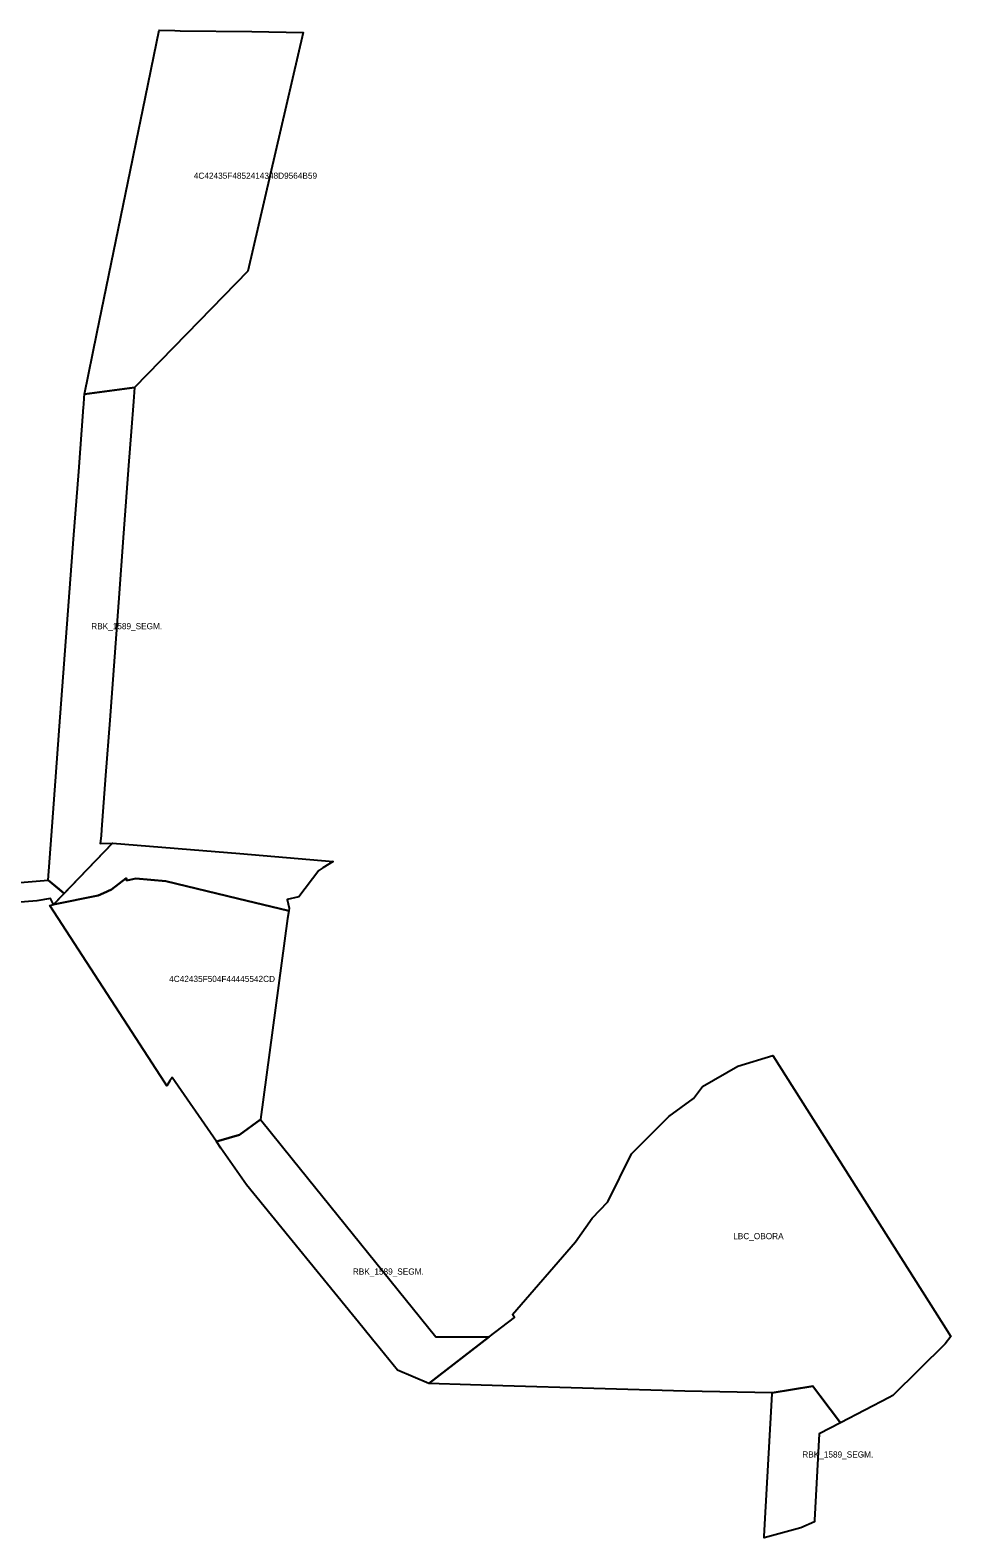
# Model space of a CAD drawing. Extents: x -541084 to -538135, y -1162553 to -1159725.
# Drawn here: x -538882 to -538135, y -1162553 to -1161330 of the extents above; entities that cross this region are included whole.
import ezdxf

# ---------------------------------------------------------------- set-up
doc = ezdxf.new("R2010")
doc.units = 0
for name, color, linetype in [('91260023', 7, 'Continuous'), ('91270013', 7, 'Continuous'), ('91270023', 7, 'Continuous'), ('91280023', 7, 'Continuous')]:
    doc.layers.add(name, color=color, linetype=linetype)

msp = doc.modelspace()

# ---------------------------------------------------------------- linework, layer by layer
at = {"layer": '91260023'}
msp.add_lwpolyline([(-538279.881, -1162436.731), (-538279.83, -1162435.82), (-538246.94, -1162430.44), (-538241.328, -1162437.916), (-538224.597, -1162460.201), (-538241.787, -1162469.145), (-538245.569, -1162539.032), (-538245.642, -1162540.385), (-538256.67, -1162545.39), (-538286.407, -1162553.479), (-538286.333, -1162552.153)], close=True, dxfattribs=at)
at = {"layer": '91270013'}
for points in [[(-538671.98, -1162042.69), (-538672.267, -1162044.823), (-538713.86, -1162034.77), (-538772.02, -1162020.88), (-538796.41, -1162018.51), (-538803.58, -1162020.1), (-538804.26, -1162018.41), (-538816.04, -1162027.52), (-538822.45, -1162030.47), (-538826.9, -1162032.51), (-538863.08, -1162039.76), (-538815.36, -1161989.8), (-538711.96, -1161998.43), (-538636.08, -1162004.76), (-538644.52, -1162009.98), (-538647.92, -1162012.08), (-538664.06, -1162033.48), (-538673.38, -1162035.73)], [(-538498.605, -1162430.067), (-538524.77, -1162429.273), (-538558.466, -1162428.25), (-538509.498, -1162390.495), (-538488.91, -1162374.62), (-538490.74, -1162372.39), (-538439.64, -1162313.45), (-538426.13, -1162294.07), (-538413.32, -1162280.83), (-538394.221, -1162241.992), (-538363.687, -1162211.712), (-538343.691, -1162197.113), (-538336.366, -1162187.229), (-538307.92, -1162170.92), (-538279.54, -1162162.191), (-538140.901, -1162380.777), (-538134.96, -1162390.143), (-538139.442, -1162396.204), (-538182.135, -1162438.109), (-538185.086, -1162439.644), (-538224.597, -1162460.201), (-538241.328, -1162437.916), (-538246.94, -1162430.44), (-538279.83, -1162435.82), (-538350.838, -1162434.55)]]:
    msp.add_lwpolyline(points, close=True, dxfattribs=at)
at = {"layer": '91270023'}
for points in [[(-538838.005, -1161625.799), (-538827.847, -1161576.385), (-538798.665, -1161434.423), (-538795.685, -1161419.928), (-538790.55, -1161394.945), (-538777.276, -1161330.371), (-538764.566, -1161330.69), (-538760.434, -1161330.846), (-538702.278, -1161331.538), (-538660.482, -1161332.245), (-538705.32, -1161525.94), (-538744.9, -1161566.45), (-538797.48, -1161620.29)], [(-538713.86, -1162034.77), (-538672.267, -1162044.823), (-538673.105, -1162051.048), (-538695.05, -1162214.09), (-538712.27, -1162226.46), (-538729.02, -1162231.4), (-538730.919, -1162231.96), (-538766.94, -1162179.94), (-538768.78, -1162182.83), (-538771.26, -1162186.72), (-538773.11, -1162183.87), (-538866.22, -1162040.39), (-538863.08, -1162039.76), (-538826.9, -1162032.51), (-538822.45, -1162030.47), (-538816.04, -1162027.52), (-538804.26, -1162018.41), (-538803.58, -1162020.1), (-538796.41, -1162018.51), (-538772.02, -1162020.88)]]:
    msp.add_lwpolyline(points, close=True, dxfattribs=at)
at = {"layer": '91280023'}
for points in [[(-538838.219, -1161628.655), (-538838.005, -1161625.799), (-538797.48, -1161620.29), (-538798.31, -1161631.51), (-538800.12, -1161655.85), (-538802.17, -1161683.57), (-538806.25, -1161738.46), (-538810.43, -1161794.77), (-538817.52, -1161890.24), (-538820.83, -1161934.92), (-538824.09, -1161978.8), (-538824.47, -1161983.94), (-538825.25, -1161990.14), (-538815.36, -1161989.8), (-538842.019, -1162017.71), (-538854.36, -1162030.631), (-538867.535, -1162019.889), (-538864.817, -1161983.614), (-538861.529, -1161939.738), (-538858.176, -1161894.991), (-538846.804, -1161743.228), (-538842.689, -1161688.306), (-538838.789, -1161636.259), (-538838.622, -1161634.028)], [(-538854.36, -1162030.631), (-538863.08, -1162039.76), (-538865.57, -1162034.76), (-538865.57, -1162034.76), (-538876.72, -1162036.74), (-538926.62, -1162040.85), (-538941.77, -1162040.48), (-538989.17, -1162037.11), (-539013.92, -1162037.13), (-539045.95, -1162041.27), (-539083.65, -1162052.18), (-539132.72, -1162068.62), (-539167.17, -1162095.62), (-539177.1, -1162076.06), (-539137.485, -1162054.397), (-539054.974, -1162026.594), (-539007.532, -1162020.741), (-538925.739, -1162024.857), (-538867.535, -1162019.889), (-538858.418, -1162027.322)], [(-538730.919, -1162231.96), (-538729.02, -1162231.4), (-538712.27, -1162226.46), (-538695.05, -1162214.09), (-538669.344, -1162245.986), (-538552.876, -1162390.495), (-538509.498, -1162390.495), (-538558.466, -1162428.25), (-538583.87, -1162417.45), (-538601.47, -1162395.9), (-538603.16, -1162393.83), (-538612.14, -1162382.82), (-538706.58, -1162267.12), (-538727.27, -1162237.23)]]:
    msp.add_lwpolyline(points, close=True, dxfattribs=at)

# ---------------------------------------------------------------- texts
at = {"layer": '91260023'}
msp.add_text('RBK_1589_SEGM.', height=5, rotation=0, dxfattribs=at).set_placement((-538255.502, -1162488.35))
at = {"layer": '91270013'}
msp.add_text('LBC_OBORA', height=5, rotation=0, dxfattribs=at).set_placement((-538311.551, -1162311.196))
at = {"layer": '91270023'}
for s, p in [('4C42435F4852414348D9564B59', (-538749.243, -1161450.938)), ('4C42435F504F44445542CD', (-538769.243, -1162102.55))]:
    msp.add_text(s, height=5, rotation=0, dxfattribs=at).set_placement(p)
at = {"layer": '91280023'}
msp.add_text('RBK_1589_SEGM.', height=5, dxfattribs=at).set_placement((-538832.508, -1161816.402))
msp.add_text('RBK_1589_SEGM.', height=5, rotation=0, dxfattribs=at).set_placement((-538620.209, -1162339.943))

doc.saveas('drawing.dxf')
